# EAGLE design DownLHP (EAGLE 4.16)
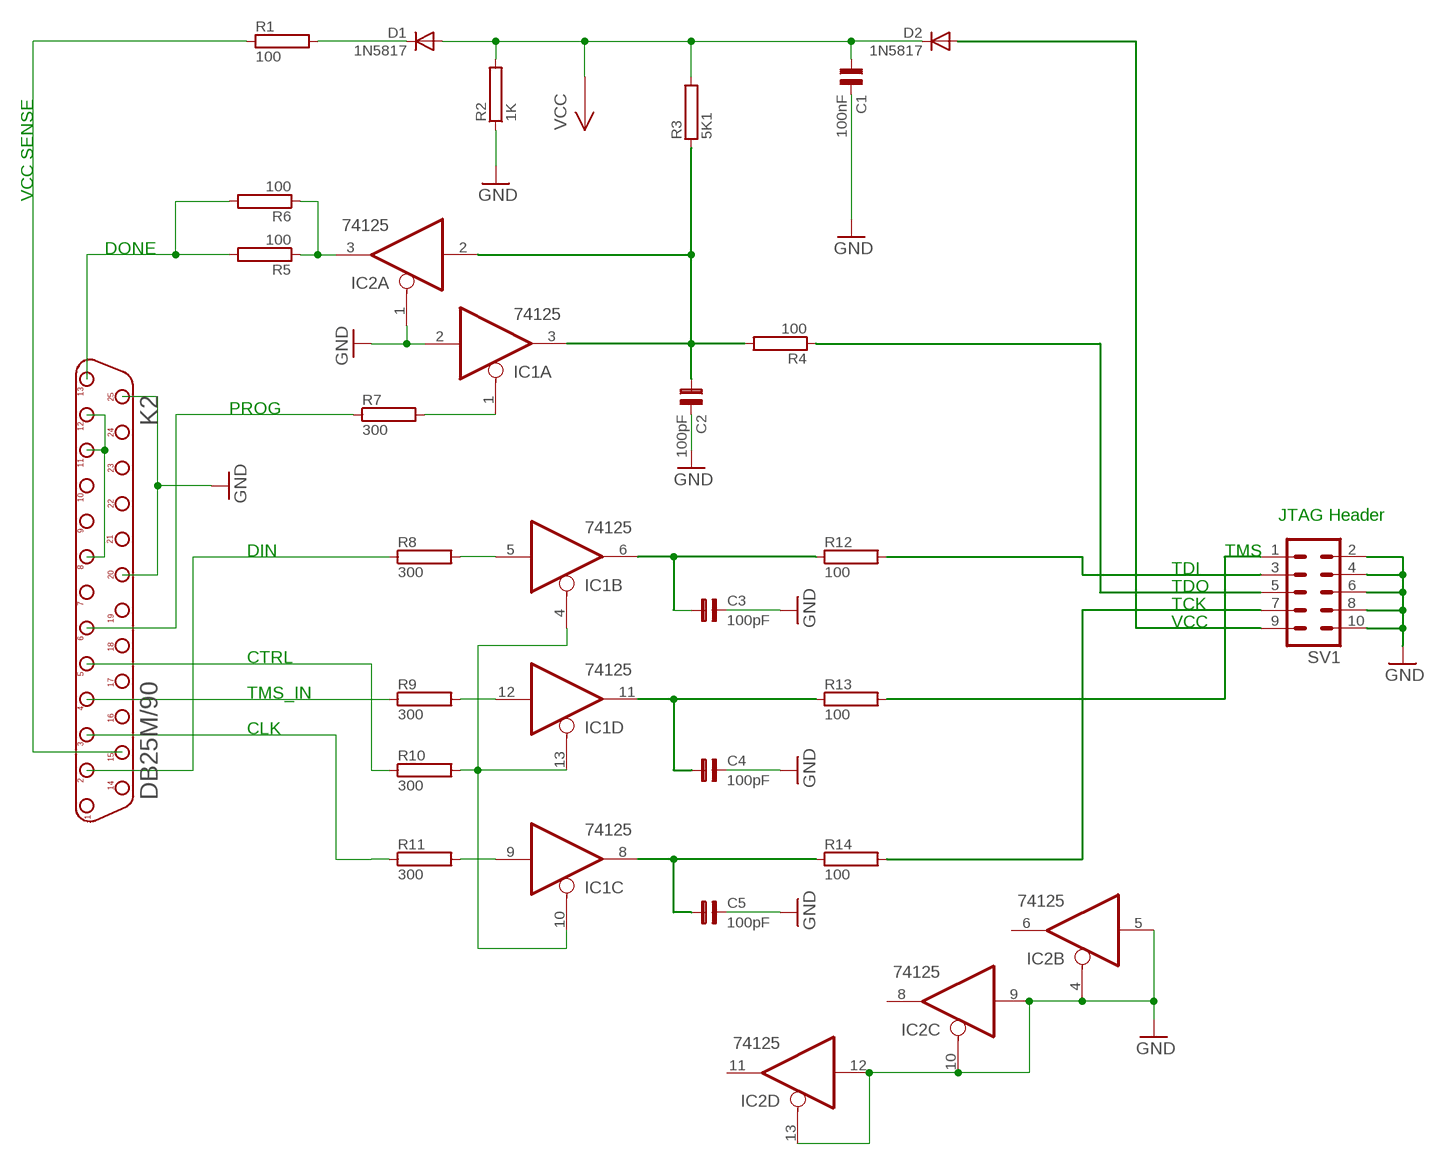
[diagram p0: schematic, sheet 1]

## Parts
C1  100nF  C5B5,5  [C5B5,5]
C2  100pF  C5B5,5  [C5B5,5]
C3  100pF  C5B5,5  [C5B5,5]
C4  100pF  C5B5,5  [C5B5,5]
C5  100pF  C5B5,5  [C5B5,5]
D1  1N5817  1N4148  [DO35-10]
D2  1N5817  1N4148  [DO35-10]
IC1  74125  [DIL14]
IC2  74125  [DIL14]
K2  DB25M/90  [D-25M/90]
R1  100  0309/10  [0309/10]
R2  1K  0309/10  [0309/10]
R3  5K1  0309/10  [0309/10]
R4  100  0309/10  [0309/10]
R5  100  0309/10  [0309/10]
R6  100  0309/10  [0309/10]
R7  300  0309/10  [0309/10]
R8  300  0309/10  [0309/10]
R9  300  0309/10  [0309/10]
R10  300  0309/10  [0309/10]
R11  300  0309/10  [0309/10]
R12  100  0309/10  [0309/10]
R13  100  0309/10  [0309/10]
R14  100  0309/10  [0309/10]
SV1  MLW10  [ML10]

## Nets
GND: C1.2 C2.2 C3.2 C4.2 C5.2 IC1.2(A:I) IC2.1(A:OE) IC2.4(B:OE) IC2.5(B:I) IC2.9(C:I) IC2.10(C:OE) IC2.12(D:I) IC2.13(D:OE) K2.20 K2.25 R2.1 SV1.2 SV1.4 SV1.6 SV1.8 SV1.10
N$2: D1.K R1.2
N$5: K2.8 K2.11 K2.12
N$6: K2.6 R7.1
N$7: IC2.3(A:O) R5.1 R6.1
N$10: IC1.5(B:I) R8.2
N$11: IC1.1(A:OE) R7.2
N$12: K2.13 R5.2 R6.2
N$13: IC1.12(D:I) R9.2
N$15: IC1.9(C:I) R11.2
N$16: IC1.4(B:OE) IC1.10(C:OE) IC1.13(D:OE) R10.2
N$17: K2.2 R8.1
N$18: K2.4 R9.1
N$19: K2.5 R10.1
N$20: K2.3 R11.1
TCK: R14.2 SV1.7
TCKX: C5.1 IC1.8(C:O) R14.1
TDI: R12.2 SV1.3
TDIX: C3.1 IC1.6(B:O) R12.1
TDO: R4.1 SV1.5
TDOX: C2.1 IC1.3(A:O) IC2.2(A:I) R3.1 R4.2
TMS: R13.2 SV1.1
TMSX: C4.1 IC1.11(D:O) R13.1
VCC: C1.1 D1.A D2.K R2.2 R3.2
VCC1: D2.A SV1.9
VCC2: K2.15 R1.1
Unconnected: IC2.6(B:O) IC2.8(C:O) IC2.11(D:O) K2.1 K2.7 K2.9 K2.10 K2.14 K2.16 K2.17 K2.18 K2.19 K2.21 K2.22 K2.23 K2.24

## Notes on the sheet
- VCC SENSE
- DONE
- PROG
- JTAG Header
- DIN | TMS
- TDI
- TDO
- TCK
- VCC
- CTRL
- TMS_IN
- CLK

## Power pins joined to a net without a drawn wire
GND: IC1.7(P:GND) IC2.7(P:GND)
VCC: IC1.14(P:VCC) IC2.14(P:VCC)

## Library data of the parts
C1-C5 = CAP:C5B5,5
D1 D2 = DIODE:1N4148
IC1 IC2 = 74XX:74125
K2 = CONNECT:DB25M/90
R1-R14 = R:0309/10
SV1 = #hacesoft:MLW10: HARTING

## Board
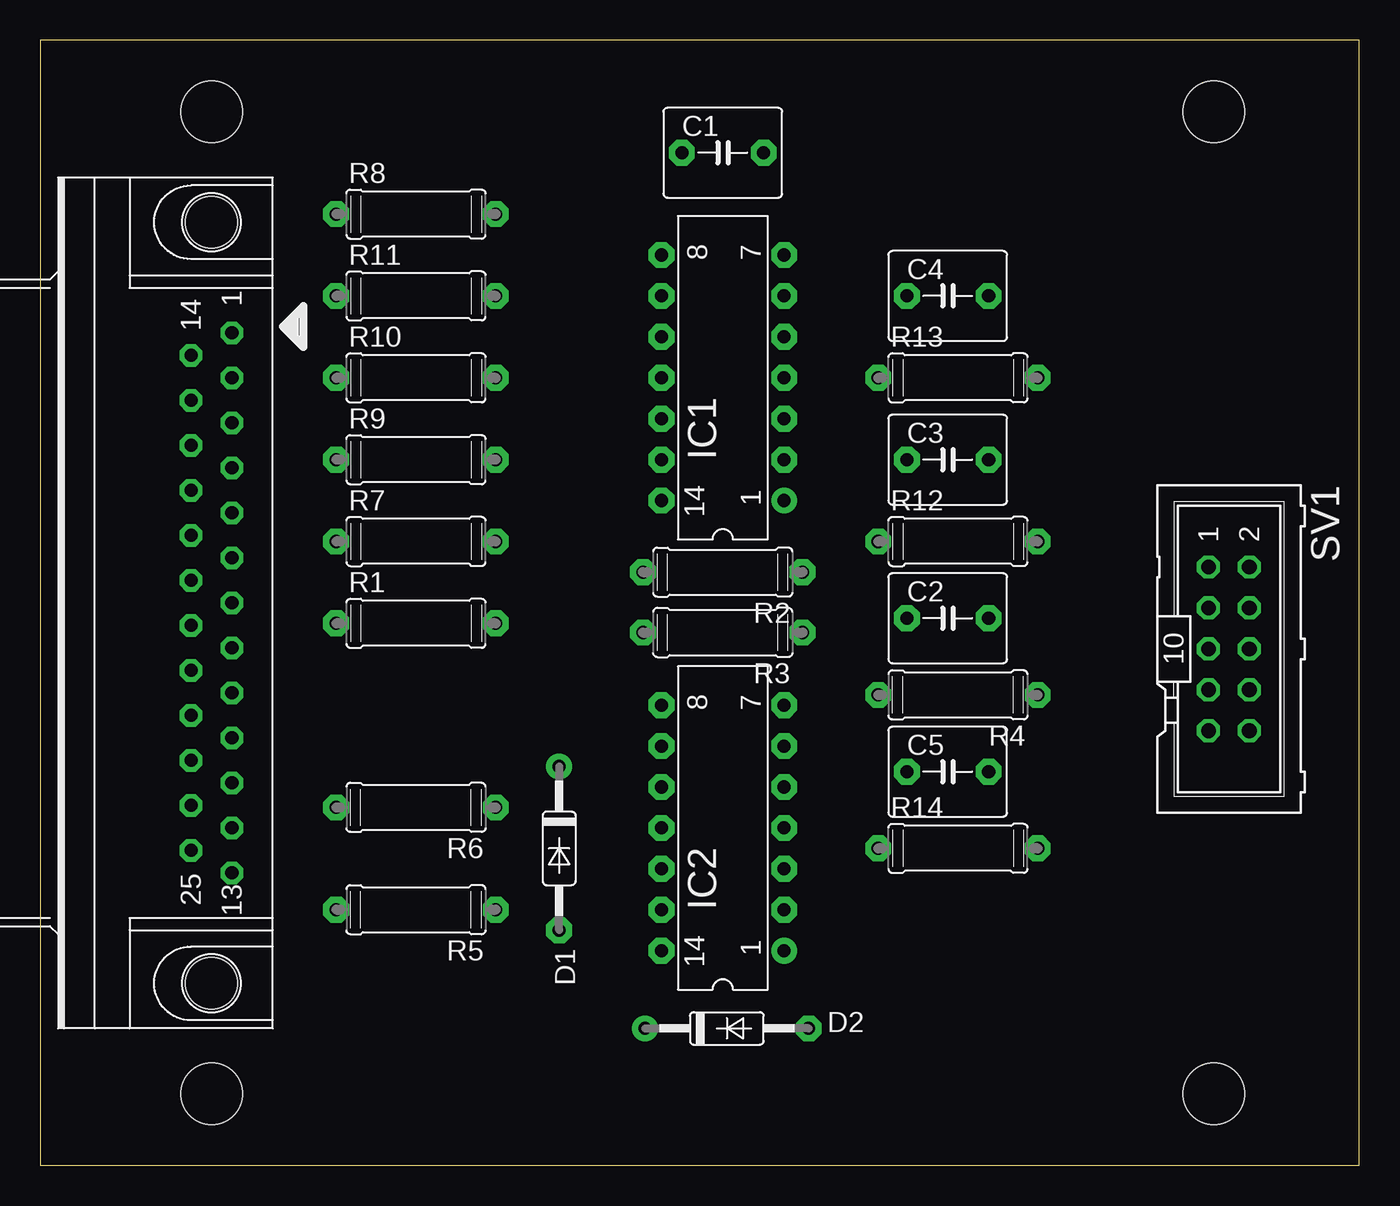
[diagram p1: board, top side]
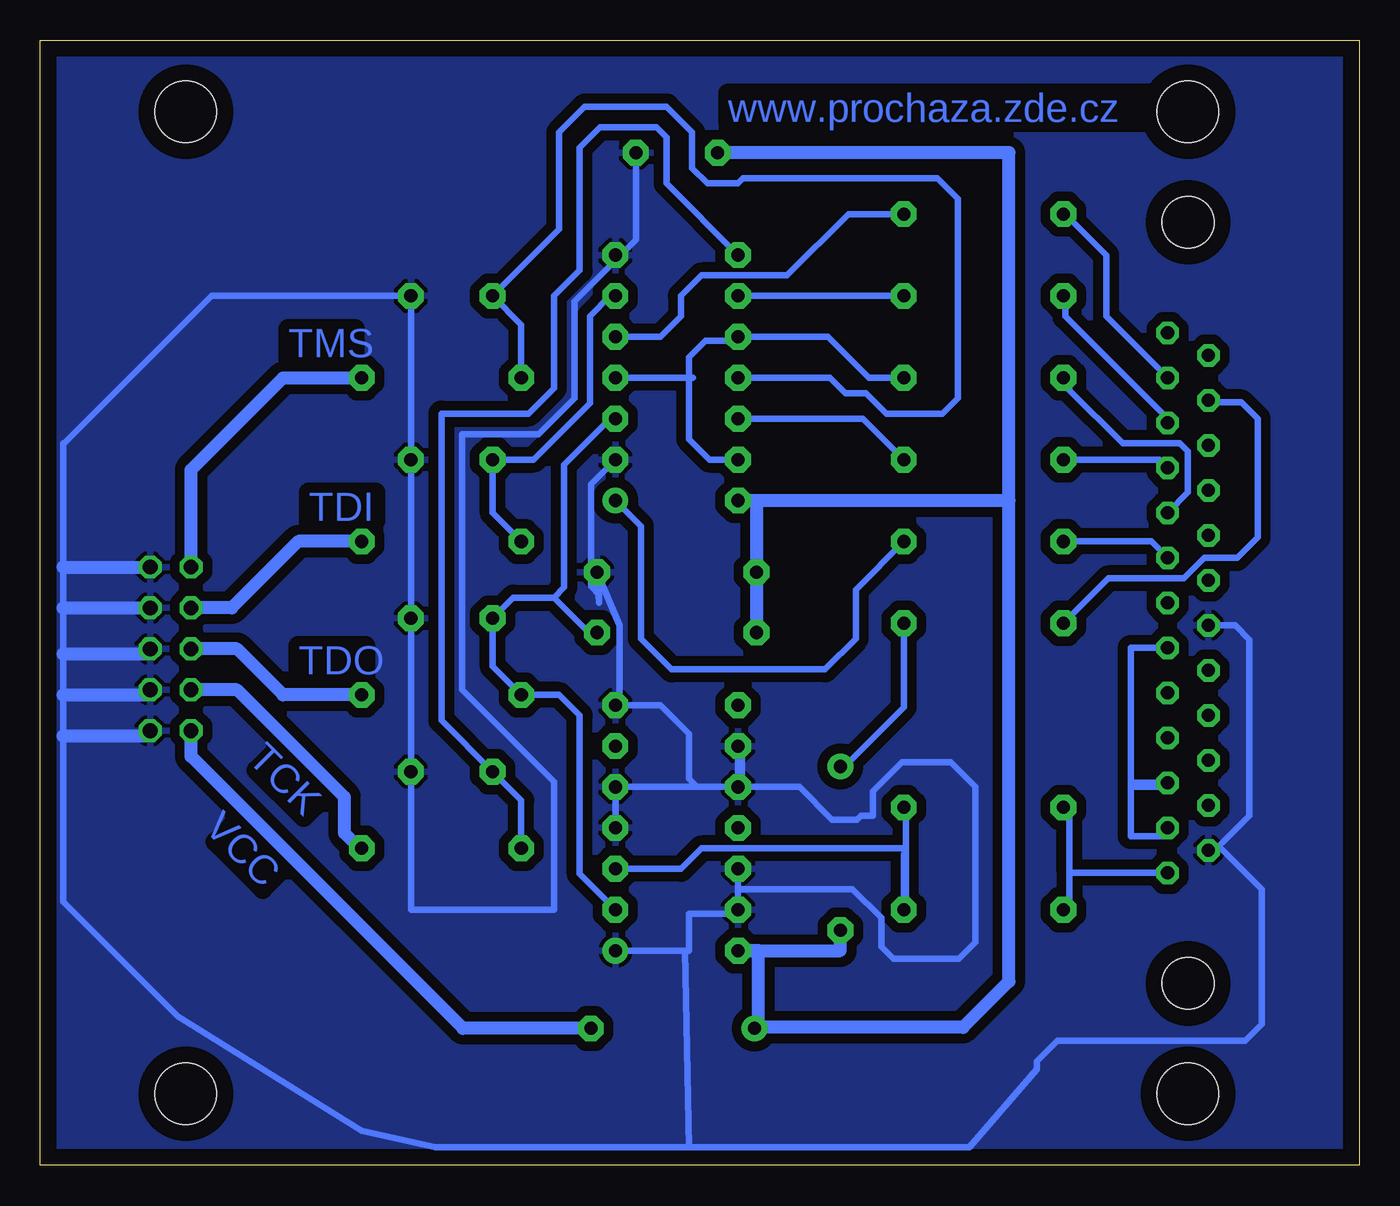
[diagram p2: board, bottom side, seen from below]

Size 81.9 x 69.84 mm. Coordinates in mm from the lower left corner, seen from the top.
Outline: 0,0 81.9,0 81.9,69.84 0,69.84 0,0
Copper layers (1*16): Top 0.035mm / dielectric 1.5mm / Bottom 0.035mm
Design rules "default": minimum track width 10mil, minimum drill 24mil, track to track 8mil, track to pad 8mil, pad to pad 8mil, via to via 8mil, smd to smd 8mil, copper to edge 40mil, drill to drill 8mil, minimum pad ring 10mil, minimum via ring 8mil, stop-mask expansion 4mil, vias tented up to drill 0mil, thermal gap 10mil
Holes 3.81 mm at 10.63,65.4 10.63,4.44 72.86,65.4 72.86,4.44

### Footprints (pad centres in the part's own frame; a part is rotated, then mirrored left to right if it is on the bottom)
C5B5,5 = drill 0.813 pad 1.6 octagon: 1 -2.54,0; 2 2.54,0
DO35-10 = drill 0.813 pad 1.6 octagon: A 5.08,0 | drill 0.813 pad 1.6 round: K -5.08,0
DIL14 = drill 0.813 pad 1.6 round: 1 -7.62,-3.81 | drill 0.813 pad 1.6 octagon: 2 -5.08,-3.81; 3 -2.54,-3.81; 4 0,-3.81; 5 2.54,-3.81; 6 5.08,-3.81; 7 7.62,-3.81; 8 7.62,3.81; 9 5.08,3.81; 10 2.54,3.81; 11 0,3.81; 12 -2.54,3.81; 13 -5.08,3.81; 14 -7.62,3.81
D-25M/90 = drill 0.813 pad 1.397 octagon: 1 16.764,-1.27; 2 13.97,-1.27; 3 11.176,-1.27; 4 8.382,-1.27; 5 5.588,-1.27; 6 2.794,-1.27; 7 0,-1.27; 8 -2.794,-1.27; 9 -5.588,-1.27; 10 -8.382,-1.27; 11 -11.176,-1.27; 12 -13.97,-1.27; 13 -16.764,-1.27; 14 15.367,1.27; 15 12.573,1.27; 16 9.779,1.27; 17 6.985,1.27; 18 4.191,1.27; 19 1.397,1.27; 20 -1.397,1.27; 21 -4.191,1.27; 22 -6.985,1.27; 23 -9.779,1.27; 24 -12.573,1.27; 25 -15.367,1.27 | hole 3.2: 23.622,0; -23.622,0
0309/10 = drill 0.813 pad 1.6 octagon: 1 -4.953,0; 2 4.953,0
ML10 = drill 0.914 octagon: 1 -5.08,-1.27; 2 -5.08,1.27; 3 -2.54,-1.27; 4 -2.54,1.27; 5 0,-1.27; 6 0,1.27; 7 2.54,-1.27; 8 2.54,1.27; 9 5.08,-1.27; 10 5.08,1.27

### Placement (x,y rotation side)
C1  42.38,62.86 0 top
C2  56.35,33.97 0 top
C3  56.35,43.81 0 top
C4  56.35,53.97 0 top
C5  56.35,24.44 0 top
D1  32.22,19.68 270 top
D2  42.63,8.5 0 top
IC1  42.38,48.89 90 top
IC2  42.38,20.95 90 top
K2  10.63,34.92 90 top
R1  23.33,33.65 0 top
R2  42.38,36.83 180 top
R3  42.38,33.08 180 top
R4  56.98,29.2 180 top
R5  23.33,15.87 180 top
R6  23.33,22.22 180 top
R7  23.33,38.73 0 top
R8  23.33,59.05 0 top
R9  23.33,43.81 0 top
R10  23.33,48.89 0 top
R11  23.33,53.97 0 top
R12  56.98,38.73 0 top
R13  56.98,48.89 0 top
R14  56.98,19.68 0 top
SV1  73.81,32.06 270 top

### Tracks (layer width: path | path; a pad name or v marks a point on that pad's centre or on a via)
GND
  Bottom 0.406: K2.20 7.71,33.52 6.82,32.63 6.82,21.71 8.85,19.68 8.6,19.68 6.06,17.14 6.06,8.76 7.07,7.74 18.76,7.74 20.03,6.47 20.03,5.96 24.22,1.14 41.62,1.14 | IC2.4 IC2.5 41.11,23.49 | IC2.10 41.11,23.49 | 38.57,26.28 IC2.9 IC2.10 | IC2.10 38.32,23.74 38.32,26.03 | 38.57,17.14 IC2.13 38.57,15.62 41.62,15.62 41.62,13.33 41.87,13.33 | 38.57,17.14 IC2.12 38.57,18.66 | 41.62,1.14 41.87,13.33 | C3.2 C2.2 C5.2 58.89,15.87 50,15.87 50,23.81 55.71,29.52 55.71,45.4 50.95,45.4 48.73,47.62 48.73,53.65 46.19,56.19 | 41.62,1.14 57.37,1.14 61.94,2.15 73.37,9.27 80.48,16.38 80.48,26.66 80.48,29.2 80.48,31.75 80.48,34.6 80.48,37.14 80.48,44.76 | 45.94,28.57 43.4,28.57 41.62,26.79 41.62,24 41.11,23.49 | 45.94,28.57 IC2.7 | IC1.2 47.71,42.29 47.71,35.94 47.21,35.43 47.21,34.92 R2.1 45.94,33.52 45.94,28.57 | 41.87,13.33 IC2.1 | IC2.10 34.76,23.49 32.73,21.46 31.2,21.46 30.95,21.71 30.19,21.71 30.19,23.24 28.41,25.01 25.36,25.01 23.84,23.49 23.84,13.84 24.85,12.82 28.92,12.82 29.68,13.58 29.68,15.36 31.46,17.14 38.57,17.14 | 80.48,44.76 80.48,44.83 | C4.2 C3.2 | C4.2 C3.2 | C4.2 71.27,53.97 80.48,44.76 | C1.2 44.92,57.46 46.19,56.19 | 46.19,56.19 IC1.7
  Bottom 0.813: 80.48,37.14 SV1.2 | 80.48,34.6 SV1.4 | SV1.6 75.4,31.75 80.48,31.75 | SV1.8 75.4,29.2 80.48,29.2 | SV1.10 75.4,26.66 80.48,26.66
  pour Bottom (isolate 0.61): 0.15,69.84 0.15,0 82.39,0 82.39,69.84
N$2
  Bottom 0.406: D1.K 31.97,24.76 28.28,28.44 R1.2
N$5
  Bottom 0.406: K2.8 14.19,32.13 14.19,23.49 11.65,23.49 11.65,23.74 K2.11 14.19,23.74 14.19,20.44 11.9,20.44 K2.12
N$6
  Bottom 0.406: K2.6 12.92,38.73 R7.1
N$7
  Bottom 0.406: R6.1 28.16,22.22 28.16,19.43 | 28.16,19.43 28.16,15.87 R5.1 28.28,19.3 28.16,19.43 | 28.16,19.43 28.41,19.68 40.86,19.68 42.13,18.41 IC2.3
N$10
  Bottom 0.406: IC1.5 43.4,51.43 42.13,52.7 42.13,53.97 40.86,55.24 35.52,55.24 31.71,59.05 R8.2
N$11
  Bottom 0.406: R7.2 31.27,35.75 31.27,32.7 33.17,30.79 42.7,30.79 44.6,32.7 44.6,39.68 IC1.1
N$12
  Bottom 0.406: R5.2 18,15.87 18,18.16 | R6.2 18,22.22 18,18.16 | K2.13 18,18.16
N$13
  Bottom 0.406: R9.2 30.82,46.35 IC1.12
N$15
  Bottom 0.406: R11.2 IC1.9
N$16
  Bottom 0.406: R10.2 30.44,48.89 32.98,51.43 IC1.10 38.82,51.18 40.6,51.18 41.62,50.16 41.62,48.89 | 41.62,48.89 41.62,45.08 40.35,43.81 IC1.13 | 41.62,48.89 41.36,48.89 | 41.62,48.89 IC1.4
N$17
  Bottom 0.406: K2.2 15.71,52.7 15.71,56.51 18.25,59.05 R8.1
N$18
  Bottom 0.406: K2.4 12.41,43.81 R9.1
N$19
  Bottom 0.406: K2.5 10.63,41.78 10.63,44.32 11.14,44.83 14.69,44.83 18,48.13 18,48.89 R10.1
N$20
  Bottom 0.406: K2.3 11.9,46.35 18.25,52.7 18.25,53.97 R11.1
TCK
  Bottom 0.813: R14.2 62.06,19.68 63.02,20.63 63.02,22.86 69.69,29.52 SV1.7
TCKX
  Bottom 0.406: R14.1 52.03,22.66 C5.1 56.98,27.62 56.98,46.67 51.59,46.67 50,48.26 50,53.97 48.41,55.56 48.41,63.18 47.14,64.45 43.65,64.45 43.02,63.81 43.02,60.95 IC1.8
TDI
  Bottom 0.813: R12.2 65.88,38.73 70,34.6 SV1.3
TDIX
  Bottom 0.406: R12.1 53.81,40.51 C3.1 51.27,43.81 47.78,47.3 47.78,52.7 46.51,53.97 IC1.6
TDO
  Bottom 0.813: R4.1 66.83,29.2 69.69,32.06 SV1.5 72.86,32.06
TDOX
  Bottom 0.406: IC2.2 48.41,18.09 48.41,27.94 49.68,29.2 R4.2 | R4.2 52.22,29.2 | R4.2 53.81,30.98 C2.1 52.54,35.24 50,35.24 | 50,35.24 49.37,35.87 49.37,43.49 46.51,46.35 IC1.3 | R3.1 47.84,33.08 50,35.24
TMS
  Bottom 0.813: R13.2 66.83,48.89 72.54,43.18 SV1.1
TMSX
  Bottom 0.406: IC1.11 32.85,48.89 31.9,47.94 30.63,47.94 29.36,46.67 25.87,46.67 24.92,47.62 24.92,60 26.19,61.27 38.25,61.27 38.57,60.95 40.48,60.95 41.43,61.91 41.43,64.13 43.02,65.72 48.09,65.72 49.68,64.13 49.68,58.1 C4.1 52.03,52.19 R13.1
VCC
  Bottom 0.813: D1.A 32.22,13.33 IC2.14 37.3,13.33 37.3,8.76 D2.K 37.3,8.25 36.98,8.57 24.6,8.57 21.74,11.43 21.74,41.27 | 21.74,41.27 37.3,41.27 | 37.3,41.27 IC1.14 | 37.3,41.27 37.43,41.27 R2.2 37.43,33.14 37.36,33.08 | 21.74,41.27 21.74,62.86 C1.1 | 37.36,33.08 37.3,33.02 | 37.36,33.08 R3.2
VCC1
  Bottom 0.813: D2.A 55.65,8.5 72.54,25.39 SV1.9
VCC2
  Bottom 0.406: R1.1 15.58,36.44 10.88,36.44 9.61,37.71 7.58,37.71 6.31,38.98 6.31,46.35 7.33,47.37 9.23,47.37 K2.15

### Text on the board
Bottom: www.prochaza.zde.cz | TMS | TDI | TDO | TCK | VCC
